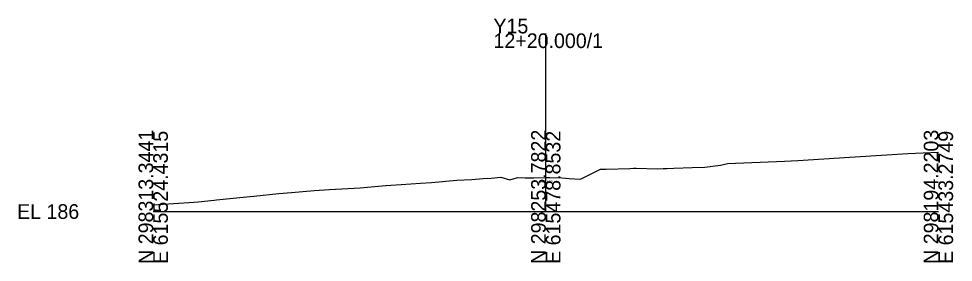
# Model space of a CAD drawing. Extents: x 517327 to 517505, y 114839 to 116885.
# Drawn here: x 517326.7 to 517505.2, y 116838.7 to 116885.2 of the extents above; entities that cross this region are included whole.
import ezdxf

# ---------------------------------------------------------------- set-up
doc = ezdxf.new("R2010")
doc.units = 0
for name, color, linetype in [('Exist XS Ground Line', 7, 'Continuous'), ('Old_Level_60', 7, 'Continuous'), ('Old_Level_63', 7, 'Continuous')]:
    doc.layers.add(name, color=color, linetype=linetype)

msp = doc.modelspace()

# ---------------------------------------------------------------- linework, layer by layer
at = {"layer": 'Exist XS Ground Line'}
for p, q in [((517475.48, 116858.07), (517485.44, 116858.75)), ((517485.44, 116858.75), (517492.48, 116859.17)), ((517492.48, 116859.17), (517496.54, 116859.41)), ((517496.54, 116859.41), (517502.36, 116859.7)), ((517455.31, 116856.74), (517457.76, 116856.81)), ((517457.76, 116856.81), (517460.72, 116857.23)), ((517460.72, 116857.23), (517461.57, 116857.39)), ((517461.57, 116857.39), (517462.05, 116857.5)), ((517462.05, 116857.5), (517472.97, 116857.95)), ((517472.97, 116857.95), (517474.23, 116858.01)), ((517474.23, 116858.01), (517475.48, 116858.07)), ((517433.98, 116854.55), (517437.78, 116856.42)), ((517437.78, 116856.42), (517438.89, 116856.45)), ((517438.89, 116856.45), (517443.42, 116856.59)), ((517443.42, 116856.59), (517444.11, 116856.61)), ((517444.11, 116856.61), (517444.62, 116856.63)), ((517444.62, 116856.63), (517448.62, 116856.52)), ((517448.62, 116856.52), (517449.76, 116856.54)), ((517449.76, 116856.54), (517450.47, 116856.58)), ((517450.47, 116856.58), (517451.81, 116856.64)), ((517451.81, 116856.64), (517455.31, 116856.74)), ((517391.87, 116852.9), (517396.78, 116853.31)), ((517396.78, 116853.31), (517399.73, 116853.53)), ((517399.73, 116853.53), (517403.4, 116853.8)), ((517403.4, 116853.8), (517405.5, 116853.93)), ((517405.5, 116853.93), (517410.38, 116854.32)), ((517410.38, 116854.32), (517413.2, 116854.49)), ((517413.2, 116854.49), (517415.41, 116854.64)), ((517415.41, 116854.64), (517416.93, 116854.74)), ((517416.93, 116854.74), (517418.76, 116854.92)), ((517418.76, 116854.92), (517420.5, 116854.42)), ((517420.5, 116854.42), (517421.15, 116854.61)), ((517421.15, 116854.61), (517421.97, 116854.86)), ((517421.97, 116854.86), (517423.45, 116854.82)), ((517423.45, 116854.82), (517424.46, 116854.79)), ((517424.46, 116854.79), (517425.1, 116854.8)), ((517425.1, 116854.8), (517427.48, 116854.87)), ((517427.48, 116854.87), (517428.14, 116854.84)), ((517428.14, 116854.84), (517430.41, 116854.76)), ((517430.41, 116854.76), (517431.83, 116854.68)), ((517431.83, 116854.68), (517433.98, 116854.55)), ((517371.57, 116851.3), (517376.37, 116851.79)), ((517376.37, 116851.79), (517378.77, 116852.02)), ((517378.77, 116852.02), (517383.1, 116852.4)), ((517383.1, 116852.4), (517386.07, 116852.55)), ((517386.07, 116852.55), (517391.87, 116852.9)), ((517352.36, 116849.61), (517360.13, 116850.12)), ((517360.13, 116850.12), (517360.95, 116850.21)), ((517360.95, 116850.21), (517364.01, 116850.55)), ((517364.01, 116850.55), (517364.44, 116850.6)), ((517364.44, 116850.6), (517370.16, 116851.17)), ((517370.16, 116851.17), (517371.57, 116851.3))]:
    msp.add_line(p, q, dxfattribs=at)
at = {"layer": 'Old_Level_63'}
for p, q in [((517427.36, 116848.36), (517427.36, 116882.36)), ((517352.36, 116848.36), (517427.36, 116848.36)), ((517427.36, 116848.36), (517502.36, 116848.36))]:
    msp.add_line(p, q, dxfattribs=at)

# ---------------------------------------------------------------- texts
at = {"layer": 'Old_Level_60'}
msp.add_text('192.499', height=0.5, dxfattribs=at).set_placement((517426.16, 116853.79))
at = {"layer": 'Old_Level_63'}
for s, p in [('Y15', (517417.36, 116882.36)), ('12+20.000/1', (517417.37, 116879.56)), ('EL 186', (517326.36, 116846.96))]:
    msp.add_text(s, height=2.8, dxfattribs=at).set_placement(p)
for s, p in [('N 298313.3441', (517352.36, 116838.36)), ('E 615524.4315', (517355.16, 116838.36)), ('N 298253.7822', (517427.36, 116838.36)), ('E 615478.8532', (517430.16, 116838.36)), ('N 298194.2203', (517502.36, 116838.36)), ('E 615433.2749', (517505.16, 116838.36))]:
    msp.add_text(s, height=2.8, rotation=90, dxfattribs=at).set_placement(p)

doc.saveas('drawing.dxf')
